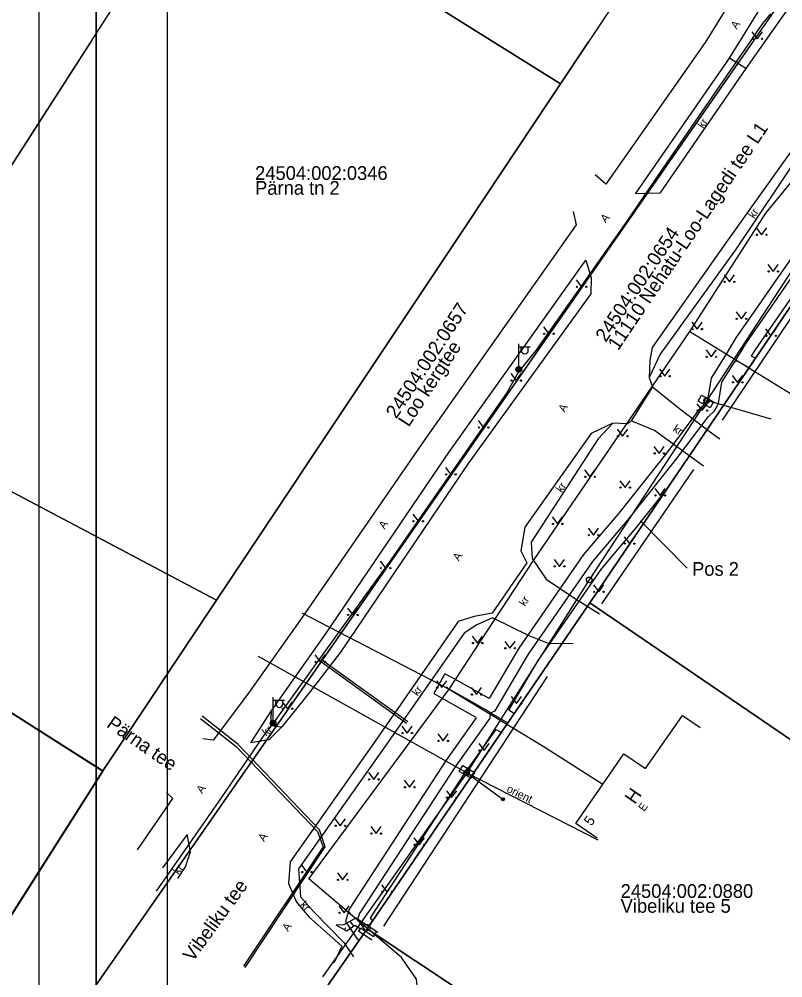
# Model space of a CAD drawing. Extents: x 553261 to 553443, y 6588794 to 6589074.
# Drawn here: x 553336.5 to 553403.3, y 6588946 to 6589029.9 of the extents above; entities that cross this region are included whole.
import ezdxf

# ---------------------------------------------------------------- set-up
doc = ezdxf.new("R2010")
doc.units = 0
for name, color, linetype in [('ELRAJATISMP', 7, 'Continuous'), ('HALJASTUS', 7, 'Continuous'), ('HOONE', 7, 'Continuous'), ('KASUTUSALA', 7, 'Continuous'), ('KPKAABEL', 7, 'Continuous'), ('MPKAABEL', 7, 'Continuous'), ('MPOHULIIN', 7, 'Continuous'), ('PIIR', 7, 'Continuous'), ('PIIRIMLEITUD', 7, 'Continuous'), ('POST', 7, 'Continuous'), ('PR_SIDE', 7, 'Continuous'), ('RAJATIS', 7, 'Continuous'), ('RELJEEF', 7, 'Continuous'), ('SITRASS', 7, 'Continuous'), ('TEE', 7, 'Continuous'), ('VORMISTUS_1', 7, 'Continuous')]:
    doc.layers.add(name, color=color, linetype=linetype)

msp = doc.modelspace()

# ---------------------------------------------------------------- linework, layer by layer
at = {"layer": 'ELRAJATISMP'}
for p, q in [((553396.633, 6588996.743), (553396.34, 6588996.222)), ((553396.869, 6588996.61), (553396.577, 6588996.089)), ((553375.732, 6588964.342), (553375.427, 6588963.83)), ((553375.966, 6588964.203), (553375.66, 6588963.691))]:
    msp.add_line(p, q, dxfattribs=at)
for points in [[(553396.23, 6588996.969), (553397.272, 6588996.384), (553396.979, 6588995.863), (553395.938, 6588996.448)], [(553375.336, 6588964.579), (553376.362, 6588963.967), (553376.056, 6588963.454), (553375.03, 6588964.066)]]:
    msp.add_lwpolyline(points, close=True, dxfattribs=at)
at = {"layer": 'HALJASTUS'}
for p, q in [((553400.647, 6589028.768), (553401.11, 6589028.161)), ((553401.11, 6589028.161), (553401.556, 6589028.768)), ((553401.025, 6589011.625), (553401.488, 6589011.018)), ((553401.488, 6589011.018), (553401.934, 6589011.625)), ((553402.039, 6589008.412), (553402.502, 6589007.806)), ((553402.502, 6589007.806), (553402.948, 6589008.412)), ((553398.203, 6589007.497), (553398.666, 6589006.891)), ((553398.666, 6589006.891), (553399.112, 6589007.497)), ((553385.257, 6589007.065), (553385.721, 6589006.458)), ((553385.721, 6589006.458), (553386.166, 6589007.065)), ((553405.456, 6589005.84), (553398.044, 6588994.79)), ((553399.253, 6589004.26), (553399.716, 6589003.654)), ((553399.716, 6589003.654), (553400.162, 6589004.26)), ((553382.398, 6589002.963), (553382.861, 6589002.356)), ((553382.861, 6589002.356), (553383.307, 6589002.963)), ((553395.38, 6589003.37), (553395.844, 6589002.764)), ((553395.844, 6589002.764), (553396.289, 6589003.37)), ((553401.841, 6589002.77), (553402.304, 6589002.163)), ((553402.304, 6589002.163), (553402.75, 6589002.77)), ((553396.625, 6589000.943), (553397.088, 6589000.336)), ((553397.088, 6589000.336), (553397.534, 6589000.943)), ((553379.539, 6588998.861), (553380.002, 6588998.254)), ((553380.002, 6588998.254), (553380.448, 6588998.861)), ((553392.558, 6588999.243), (553393.021, 6588998.636)), ((553393.021, 6588998.636), (553393.467, 6588999.243)), ((553398.925, 6588998.708), (553399.389, 6588998.101)), ((553399.389, 6588998.101), (553399.834, 6588998.708)), ((553395.83, 6588996.233), (553396.294, 6588995.627)), ((553396.294, 6588995.627), (553396.739, 6588996.233)), ((553376.68, 6588994.759), (553377.143, 6588994.153)), ((553377.143, 6588994.153), (553377.589, 6588994.759)), ((553388.86, 6588993.99), (553389.323, 6588993.383)), ((553389.323, 6588993.383), (553389.769, 6588993.99)), ((553392.065, 6588992.491), (553392.528, 6588991.885)), ((553392.528, 6588991.885), (553392.974, 6588992.491)), ((553373.82, 6588990.658), (553374.284, 6588990.051)), ((553374.284, 6588990.051), (553374.729, 6588990.658)), ((553386.003, 6588990.441), (553386.467, 6588989.835)), ((553386.467, 6588989.835), (553386.912, 6588990.441)), ((553395.523, 6588990.474), (553387.478, 6588978.735)), ((553389.075, 6588989.498), (553389.538, 6588988.891)), ((553389.538, 6588988.891), (553389.984, 6588989.498)), ((553392.138, 6588988.816), (553392.601, 6588988.209)), ((553392.601, 6588988.209), (553393.047, 6588988.816)), ((553370.961, 6588986.556), (553371.424, 6588985.949)), ((553371.424, 6588985.949), (553371.87, 6588986.556)), ((553383.169, 6588986.322), (553383.632, 6588985.716)), ((553383.632, 6588985.716), (553384.078, 6588986.322)), ((553386.303, 6588985.337), (553386.766, 6588984.73)), ((553386.766, 6588984.73), (553387.212, 6588985.337)), ((553389.457, 6588984.595), (553389.92, 6588983.988)), ((553389.92, 6588983.988), (553390.366, 6588984.595)), ((553368.102, 6588982.454), (553368.565, 6588981.847)), ((553368.565, 6588981.847), (553369.011, 6588982.454)), ((553383.326, 6588982.607), (553383.79, 6588982)), ((553383.79, 6588982), (553384.235, 6588982.607)), ((553386.776, 6588980.375), (553387.239, 6588979.768)), ((553387.239, 6588979.768), (553387.685, 6588980.375)), ((553365.243, 6588978.352), (553365.706, 6588977.745)), ((553365.706, 6588977.745), (553366.152, 6588978.352)), ((553376.168, 6588975.898), (553376.631, 6588975.291)), ((553376.631, 6588975.291), (553377.077, 6588975.898)), ((553379.005, 6588975.44), (553379.468, 6588974.833)), ((553379.468, 6588974.833), (553379.914, 6588975.44)), ((553362.383, 6588974.25), (553362.847, 6588973.644)), ((553362.847, 6588973.644), (553363.292, 6588974.25)), ((553373.04, 6588971.997), (553373.503, 6588971.39)), ((553373.503, 6588971.39), (553373.949, 6588971.997)), ((553376.076, 6588971.387), (553376.54, 6588970.78)), ((553376.54, 6588970.78), (553376.985, 6588971.387)), ((553379.566, 6588970.613), (553380.029, 6588970.006)), ((553380.029, 6588970.006), (553380.475, 6588970.613)), ((553359.524, 6588970.149), (553359.988, 6588969.542)), ((553359.988, 6588969.542), (553360.433, 6588970.149)), ((553370.005, 6588968.025), (553370.468, 6588967.419)), ((553370.468, 6588967.419), (553370.914, 6588968.025)), ((553373.148, 6588967.334), (553373.612, 6588966.727)), ((553373.612, 6588966.727), (553374.057, 6588967.334)), ((553376.734, 6588966.492), (553377.197, 6588965.886)), ((553377.197, 6588965.886), (553377.643, 6588966.492)), ((553367.08, 6588963.97), (553367.544, 6588963.363)), ((553367.544, 6588963.363), (553367.989, 6588963.97)), ((553370.22, 6588963.281), (553370.684, 6588962.674)), ((553370.684, 6588962.674), (553371.129, 6588963.281)), ((553373.902, 6588962.372), (553374.365, 6588961.765)), ((553374.365, 6588961.765), (553374.811, 6588962.372)), ((553364.155, 6588959.915), (553364.619, 6588959.308)), ((553364.619, 6588959.308), (553365.064, 6588959.915)), ((553367.292, 6588959.228), (553367.755, 6588958.622)), ((553367.755, 6588958.622), (553368.201, 6588959.228)), ((553371.069, 6588958.251), (553371.533, 6588957.645)), ((553371.533, 6588957.645), (553371.978, 6588958.251)), ((553361.231, 6588955.859), (553361.694, 6588955.253)), ((553361.694, 6588955.253), (553362.14, 6588955.859)), ((553364.364, 6588955.175), (553364.827, 6588954.569)), ((553364.827, 6588954.569), (553365.273, 6588955.175)), ((553368.237, 6588954.131), (553368.701, 6588953.524)), ((553368.701, 6588953.524), (553369.146, 6588954.131)), ((553364.493, 6588952.299), (553364.956, 6588951.693)), ((553364.956, 6588951.693), (553365.402, 6588952.299))]:
    msp.add_line(p, q, dxfattribs=at)
msp.add_lwpolyline([(553382.726, 6588972.365), (553376.514, 6588962.896), (553368.408, 6588950.506)], dxfattribs=at)
for centre in [(553400.709, 6589028.161), (553401.538, 6589028.161), (553401.087, 6589011.018), (553401.916, 6589011.018), (553402.101, 6589007.806), (553402.93, 6589007.806), (553385.32, 6589006.458), (553386.148, 6589006.458), (553398.265, 6589006.891), (553399.094, 6589006.891), (553399.315, 6589003.654), (553400.144, 6589003.654), (553382.46, 6589002.356), (553383.289, 6589002.356), (553395.443, 6589002.764), (553396.271, 6589002.764), (553401.903, 6589002.163), (553402.732, 6589002.163), (553396.687, 6589000.336), (553397.516, 6589000.336), (553379.601, 6588998.254), (553380.43, 6588998.254), (553392.62, 6588998.636), (553393.449, 6588998.636), (553398.988, 6588998.101), (553399.816, 6588998.101), (553395.893, 6588995.627), (553396.722, 6588995.627), (553376.742, 6588994.153), (553377.571, 6588994.153), (553388.922, 6588993.383), (553389.751, 6588993.383), (553392.127, 6588991.885), (553392.956, 6588991.885), (553373.883, 6588990.051), (553374.711, 6588990.051), (553386.066, 6588989.835), (553386.894, 6588989.835), (553389.137, 6588988.891), (553389.966, 6588988.891), (553392.2, 6588988.209), (553393.029, 6588988.209), (553371.023, 6588985.949), (553371.852, 6588985.949), (553383.231, 6588985.716), (553384.06, 6588985.716), (553386.365, 6588984.73), (553387.194, 6588984.73), (553389.519, 6588983.988), (553390.348, 6588983.988), (553383.389, 6588982), (553384.217, 6588982), (553368.164, 6588981.847), (553368.993, 6588981.847), (553386.838, 6588979.768), (553387.667, 6588979.768), (553365.305, 6588977.745), (553366.134, 6588977.745), (553376.23, 6588975.291), (553377.059, 6588975.291), (553379.067, 6588974.833), (553379.896, 6588974.833), (553362.446, 6588973.644), (553363.275, 6588973.644), (553373.102, 6588971.39), (553373.931, 6588971.39), (553376.139, 6588970.78), (553376.968, 6588970.78), (553359.587, 6588969.542), (553360.415, 6588969.542), (553379.628, 6588970.006), (553380.457, 6588970.006), (553370.067, 6588967.419), (553370.896, 6588967.419), (553373.211, 6588966.727), (553374.039, 6588966.727), (553376.796, 6588965.886), (553377.625, 6588965.886), (553367.142, 6588963.363), (553367.971, 6588963.363), (553370.283, 6588962.674), (553371.111, 6588962.674), (553373.964, 6588961.765), (553374.793, 6588961.765), (553364.218, 6588959.308), (553365.047, 6588959.308), (553367.354, 6588958.622), (553368.183, 6588958.622), (553371.132, 6588957.645), (553371.961, 6588957.645), (553361.293, 6588955.253), (553362.122, 6588955.253), (553364.426, 6588954.569), (553365.255, 6588954.569), (553368.3, 6588953.524), (553369.128, 6588953.524), (553364.555, 6588951.693), (553365.384, 6588951.693)]:
    msp.add_circle(centre, 0.055, dxfattribs=at)
at = {"layer": 'HOONE'}
msp.add_lwpolyline([(553387.1, 6588958.21), (553385.22, 6588959.51), (553389.44, 6588965.6), (553391.32, 6588964.3), (553394.57, 6588968.96), (553396.12, 6588967.9)], dxfattribs=at)
at = {"layer": 'KASUTUSALA'}
msp.add_lwpolyline([(553404.707, 6589009.859), (553399.243, 6589001.994), (553398.806, 6589001.279), (553398.467, 6589000.724), (553398.067, 6589000.069), (553397.062, 6588998.477), (553396.76, 6588996.579), (553396.566, 6588996.228), (553396.097, 6588995.804), (553393.172, 6588991.911), (553388.98, 6588986.655), (553385.917, 6588983.034), (553380.244, 6588974.844), (553377.649, 6588970.442), (553374.649, 6588972.122), (553373.776, 6588972.611), (553372.799, 6588970.866), (553373.671, 6588970.378), (553376.425, 6588968.835), (553376.522, 6588968.745), (553373.871, 6588965.038), (553365.384, 6588952.009), (553365.067, 6588950.917), (553366.023, 6588949.539), (553366.236, 6588949.233), (553366.97, 6588950.29), (553367.45, 6588950.992), (553367.274, 6588951.246), (553375.523, 6588963.91), (553378.26, 6588967.737), (553378.715, 6588967.474), (553379.847, 6588969.129), (553379.782, 6588969.167), (553379.362, 6588969.41), (553381.93, 6588973.766), (553387.507, 6588981.816), (553390.525, 6588985.385), (553393.109, 6588988.624), (553398.874, 6588997.139), (553399.821, 6588998.537), (553400.943, 6589000.194), (553400.921, 6589000.208), (553400.613, 6589000.401), (553400.919, 6589000.902), (553406.271, 6589008.606)], dxfattribs=at)
at = {"layer": 'KPKAABEL'}
for points in [[(553352.396, 6588968.693), (553355.51, 6588966.24), (553362.63, 6588958.79), (553363.12, 6588957.47), (553356.16, 6588947.024)], [(553356.304, 6588946.897), (553363.29, 6588957.47), (553362.79, 6588958.96), (553355.67, 6588966.41), (553352.533, 6588968.882)]]:
    msp.add_lwpolyline(points, dxfattribs=at)
at = {"layer": 'MPKAABEL'}
msp.add_line((553375.68, 6588963.935), (553387.15, 6588958.07), dxfattribs=at)
for points in [[(553402.257, 6589030.331), (553401.56, 6589029.493), (553392.545, 6589016.411), (553389.649, 6589012.117), (553381.74, 6589000.899), (553380.207, 6588999.016), (553379.219, 6588997.231), (553369.043, 6588982.568), (553359.555, 6588969.425), (553358.783, 6588968.309), (553357.879, 6588967.138), (553354.209, 6588961.743), (553348.518, 6588953.579)], [(553402.257, 6589030.331), (553401.56, 6589029.493), (553392.545, 6589016.411), (553389.649, 6589012.117), (553381.74, 6589000.899), (553380.207, 6588999.016), (553379.219, 6588997.231), (553369.043, 6588982.568), (553359.555, 6588969.425), (553358.783, 6588968.309), (553357.879, 6588967.138), (553354.209, 6588961.743), (553348.518, 6588953.579)], [(553362.874, 6588973.709), (553370.414, 6588968.272)], [(553362.978, 6588973.851), (553370.524, 6588968.422)]]:
    msp.add_lwpolyline(points, dxfattribs=at)
at = {"layer": 'MPOHULIIN'}
for points in [[(553407.936, 6589013.677), (553396.681, 6588996.514), (553396.681, 6588996.514), (553386.407, 6588980.817), (553375.68, 6588963.935), (553363.057, 6588946.078)], [(553402.318, 6588994.883), (553396.681, 6588996.514)], [(553375.68, 6588963.935), (553357.463, 6588974.128)]]:
    msp.add_lwpolyline(points, dxfattribs=at)
at = {"layer": 'PIIR'}
for points in [[(553398.49, 6589073.95), (553400.8, 6589049.61), (553383.89, 6589024.22), (553352.89, 6589043.6), (553339.8, 6589053.09), (553358.63, 6589067.61)], [(553352.89, 6589043.6), (553383.89, 6589024.22), (553353.8, 6588979.04), (553322.14, 6588995.79)], [(553343.85, 6588964.09), (553318.22, 6588923.75), (553292.18, 6588941.51), (553317.25, 6588980.99)], [(553366.97, 6588950.29), (553386.47, 6588978.82), (553419.97, 6588955.97), (553401.3, 6588927.47)], [(553401.3, 6588927.47), (553381.71, 6588898.9), (553347.5, 6588922.26), (553366.97, 6588950.29)]]:
    msp.add_lwpolyline(points, close=True, dxfattribs=at)
for points in [[(553269.61, 6588823.387), (553275.1, 6588838.43), (553306.34, 6588891.77), (553312.93, 6588901.87), (553404.2, 6589032.89), (553408.34, 6589040.49)], [(553431.953, 6589028.538), (553426.41, 6589023.65), (553416.94, 6589023.42), (553405.24, 6589006.54), (553386.47, 6588978.82), (553366.97, 6588950.29), (553347.5, 6588922.26), (553328.32, 6588893.48), (553310.97, 6588866.48), (553295.9, 6588840.93), (553293.3, 6588836.47), (553287.77, 6588819.195)], [(553400.72, 6589027.895), (553312.93, 6588901.87), (553306.34, 6588891.77), (553275.1, 6588838.43), (553278.46, 6588847.64), (553296.63, 6588881.81), (553313.47, 6588914.66), (553318.15, 6588923.71), (553343.84, 6588964.11), (553353.8, 6588979.04), (553383.89, 6589024.22), (553386.338, 6589027.895)], [(553292.469, 6589027.895), (553298.08, 6589020.22), (553322.14, 6588995.79), (553353.8, 6588979.04), (553343.84, 6588964.11), (553317.25, 6588980.99), (553291.21, 6588997.51), (553290.08, 6589002.89), (553293.13, 6589008.65), (553286.68, 6589017.98), (553280.69, 6589021.2), (553275.792, 6589027.895)], [(553342.789, 6589027.895), (553322.14, 6588995.79), (553298.08, 6589020.22), (553292.469, 6589027.895)], [(553434.11, 6588976.398), (553419.97, 6588955.97), (553386.47, 6588978.82), (553405.24, 6589006.54), (553434.11, 6588987.72)]]:
    msp.add_lwpolyline(points, dxfattribs=at)
at = {"layer": 'PIIRIMLEITUD'}
msp.add_circle((553366.946, 6588950.407), 0.285, dxfattribs=at)
at = {"layer": 'POST'}
for p, q in [((553380.235, 6588999.468), (553380.235, 6589001.468)), ((553380.235, 6589001.218), (553381.235, 6589001.218)), ((553380.462, 6589000.897), (553380.462, 6589001.218)), ((553381.075, 6589000.897), (553381.075, 6589001.218)), ((553380.235, 6588999.218), (553380.235, 6588999.218)), ((553358.743, 6588968.542), (553358.743, 6588970.542)), ((553358.743, 6588970.292), (553359.743, 6588970.292)), ((553358.97, 6588969.971), (553358.97, 6588970.292)), ((553359.582, 6588969.971), (553359.582, 6588970.292)), ((553358.743, 6588968.292), (553358.743, 6588968.292))]:
    msp.add_line(p, q, dxfattribs=at)
msp.add_lwpolyline([(553375.68, 6588963.935), (553378.85, 6588961.62)], dxfattribs=at)
for centre, radius in [((553380.235, 6588999.218), 0.25), ((553380.235, 6588999.218), 0.225), ((553380.235, 6588999.218), 0.2), ((553380.235, 6588999.218), 0.175), ((553380.235, 6588999.218), 0.15), ((553380.235, 6588999.218), 0.125), ((553380.235, 6588999.218), 0.1), ((553380.235, 6588999.218), 0.075), ((553380.235, 6588999.218), 0.05), ((553380.235, 6588999.218), 0.025), ((553396.681, 6588996.514), 0.25), ((553386.407, 6588980.817), 0.25), ((553358.743, 6588968.292), 0.25), ((553358.743, 6588968.292), 0.225), ((553358.743, 6588968.292), 0.2), ((553358.743, 6588968.292), 0.175), ((553358.743, 6588968.292), 0.15), ((553358.743, 6588968.292), 0.125), ((553358.743, 6588968.292), 0.1), ((553358.743, 6588968.292), 0.075), ((553358.743, 6588968.292), 0.05), ((553358.743, 6588968.292), 0.025), ((553375.68, 6588963.935), 0.25), ((553378.85, 6588961.62), 0.125), ((553378.85, 6588961.62), 0.105), ((553378.85, 6588961.62), 0.0851), ((553378.85, 6588961.62), 0.0651), ((553378.85, 6588961.62), 0.0451), ((553378.85, 6588961.62), 0.0251), ((553378.85, 6588961.62), 0.00511)]:
    msp.add_circle(centre, radius, dxfattribs=at)
for centre in [(553380.768, 6589000.897), (553359.276, 6588969.971)]:
    msp.add_arc(centre, 0.306, 180, 0, dxfattribs=at)
at = {"layer": 'PR_SIDE'}
for points in [[(553399.139, 6588999.905), (553400.081, 6589001.448), (553405.489, 6589009.233), (553408.532, 6589012.542), (553409.554, 6589014.823), (553413.47, 6589020.515), (553414.867, 6589022.525), (553415.143, 6589022.641), (553415.48, 6589022.56), (553416.124, 6589022.242)], [(553377.777, 6588969.173), (553378.164, 6588969.346), (553381.087, 6588974.305), (553386.712, 6588982.425), (553389.753, 6588986.02), (553393.963, 6588991.298), (553396.839, 6588995.127), (553397.36, 6588995.599), (553397.72, 6588996.248), (553398.017, 6588998.116), (553398.919, 6588999.544), (553399.139, 6588999.905)], [(553399.139, 6588999.905), (553399.361, 6588999.986), (553399.805, 6588999.727), (553400.389, 6588999.361)], [(553377.777, 6588969.173), (553377.364, 6588969.456), (553374.16, 6588971.25)], [(553366.845, 6588950.11), (553366.16, 6588951.096), (553366.303, 6588951.587), (553374.697, 6588964.474), (553377.731, 6588968.716), (553377.777, 6588969.173)], [(553377.777, 6588969.173), (553379.281, 6588968.302)]]:
    msp.add_lwpolyline(points, dxfattribs=at)
at = {"layer": 'RAJATIS'}
msp.add_lwpolyline([(553367.515, 6588949.587), (553366.408, 6588950.341), (553366.224, 6588950.119), (553367.381, 6588949.337)], dxfattribs=at)
at = {"layer": 'RELJEEF'}
for p, q in [((553365.809, 6588950.512), (553365.487, 6588950.96)), ((553364.981, 6588950.193), (553365.097, 6588950.403)), ((553366.687, 6588950.151), (553366.748, 6588950.25)), ((553367.515, 6588949.587), (553367.789, 6588950.04))]:
    msp.add_line(p, q, dxfattribs=at)
for points in [[(553367.903, 6588949.966), (553365.97, 6588951.233), (553364.905, 6588950.631), (553364.255, 6588950.595)], [(553366.362, 6588950.285), (553365.891, 6588950.571), (553365.198, 6588950.073), (553364.255, 6588950.595)]]:
    msp.add_lwpolyline(points, dxfattribs=at)
at = {"layer": 'SITRASS'}
for points in [[(553371.515, 6588943.799), (553371.28, 6588945.87), (553369.98, 6588947.79), (553361.86, 6588954.66), (553374.16, 6588971.25), (553381.59, 6588982.6), (553395.2, 6589002.56), (553401.87, 6589012.9), (553411.9, 6589025.12), (553419.37, 6589020.03), (553424.388, 6589016.672)], [(553395.2, 6589002.56), (553403.55, 6588997.42), (553409.017, 6588994.134)], [(553361.245, 6588977.942), (553374.16, 6588971.25)], [(553374.16, 6588971.25), (553382.37, 6588966.28), (553387.607, 6588962.955)]]:
    msp.add_lwpolyline(points, dxfattribs=at)
at = {"layer": 'TEE'}
msp.add_line((553400.105, 6589025.557), (553398.689, 6589026.473), dxfattribs=at)
for points in [[(553402.191, 6589038.206), (553399.566, 6589032.707), (553396.547, 6589027.841), (553387.864, 6589015.454), (553386.933, 6589016.246)], [(553407.629, 6589036.196), (553403.138, 6589029.864), (553400.105, 6589025.557), (553392.597, 6589014.643), (553390.443, 6589014.592), (553398.689, 6589026.473), (553401.561, 6589031.119), (553404.616, 6589037.375)], [(553404.003, 6589018.245), (553398.361, 6589010.315), (553391.908, 6589001.161), (553391.7, 6589000), (553391.649, 6588998.522), (553391.943, 6588997.694), (553390.065, 6588994.733), (553389.77, 6588994.47), (553388.465, 6588994.527), (553386.58, 6588993.615), (553380.779, 6588985.433), (553380.409, 6588983.357), (553380.953, 6588982.306), (553377.917, 6588977.901), (553376.347, 6588977.601), (553374.927, 6588977.176), (553367.932, 6588967.072), (553360.219, 6588956.151), (553360.094, 6588954.264), (553360.792, 6588952.606), (553361.86, 6588951.349), (553364.755, 6588948.771), (553364.058, 6588947.276)], [(553405.552, 6589018.694), (553404.957, 6589018.27), (553399.27, 6589009.775), (553392.603, 6589000.577), (553391.649, 6588998.522)], [(553384.999, 6589013.041), (553385.27, 6589011.887), (553372.005, 6588993.105), (553361.24, 6588977.509), (553356.493, 6588970.798), (553353.497, 6588966.803), (553352.596, 6588966.904)], [(553356.791, 6588966.553), (553358.58, 6588969.335), (553363.328, 6588976.079), (553374.183, 6588992.053), (553386.117, 6589008.789), (553386.573, 6589007.238), (553386.533, 6589005.842), (553375.804, 6588990.988), (553364.649, 6588974.479), (553361.905, 6588970.943), (553359.496, 6588967.969), (553358.373, 6588966.828), (553356.791, 6588966.553)], [(553391.943, 6588997.694), (553394.325, 6588995.774), (553396.897, 6588993.829), (553397.834, 6588993.162)], [(553388.465, 6588994.527), (553387.194, 6588993.145), (553381.324, 6588984.115), (553381.396, 6588982.694), (553382.626, 6588980.866), (553385.197, 6588979.163), (553387.298, 6588977.857)], [(553396.391, 6588990.755), (553392.13, 6588993.886), (553390.065, 6588994.733)], [(553385.006, 6588975.238), (553382.907, 6588975.212), (553381.135, 6588975.914), (553377.931, 6588977.503), (553376.554, 6588976.877), (553375.447, 6588976.158), (553368.852, 6588966.683), (553360.976, 6588955.531), (553361.138, 6588953.099), (553362.277, 6588951.811), (553364.93, 6588949.104), (553365.77, 6588947.839)], [(553358.58, 6588969.335), (553358.507, 6588968.074), (553359.496, 6588967.969)], [(553346.873, 6588957.197), (553349.953, 6588961.703), (553349.424, 6588962.204)], [(553350.411, 6588954.688), (553351.082, 6588955.72), (553351.518, 6588957.009), (553351.228, 6588958.542), (553349.059, 6588955.637)]]:
    msp.add_lwpolyline(points, dxfattribs=at)
at = {"layer": 'VORMISTUS_1'}
msp.add_line((553390.904, 6588985.993), (553394.98, 6588981.844), dxfattribs=at)
for points in [[(553338.255, 6589062.04), (553443.255, 6589062.04), (553443.255, 6588913.54), (553338.255, 6588913.54)], [(553343.255, 6588919.04), (553438.255, 6588919.04), (553438.255, 6589056.54), (553343.255, 6589056.54)], [(553343.255, 6589056.54), (553438.255, 6589056.54), (553438.255, 6588919.04), (553343.255, 6588919.04)], [(553432.005, 6588932.04), (553349.505, 6588932.04), (553349.505, 6589037.04), (553432.005, 6589037.04)]]:
    msp.add_lwpolyline(points, close=True, dxfattribs=at)

# ---------------------------------------------------------------- texts
at = {"layer": 'HOONE'}
for s, height, rotation, p in [('H', 1.2, 55.41411, (553390.402, 6588961.108)), ('E', 0.7, 55.41411, (553391.221, 6588960.499)), ('5', 0.9, 55.23477, (553386.597, 6588959.226))]:
    msp.add_text(s, height=height, rotation=rotation, dxfattribs=at).set_placement(p)
at = {"layer": 'MPKAABEL'}
msp.add_text('orient', height=0.7, rotation=333.19754, dxfattribs=at).set_placement((553379.115, 6588962.311))
at = {"layer": 'PIIR'}
for s, rotation, p in [('11110 Nehatu-Loo-Lagedi tee L1', 55.98329, (553388.93, 6589000.819)), ('24504:002:0654', 55.98329, (553387.853, 6589001.546)), ('24504:002:0657', 56.69618, (553369.517, 6588994.847)), ('Loo kergtee', 56.69618, (553370.604, 6588994.133))]:
    msp.add_text(s, height=1.2, rotation=rotation, dxfattribs=at).set_placement(p)
for s, p in [('24504:002:0346', (553357.163, 6589015.815)), ('Pärna tn 2', (553357.163, 6589014.515)), ('24504:002:0880', (553389.153, 6588952.992)), ('Vibeliku tee 5', (553389.153, 6588951.692))]:
    msp.add_text(s, height=1.2, dxfattribs=at).set_placement(p)
at = {"layer": 'TEE'}
for s, height, rotation, p in [('A', 0.7, 55.40858, (553399.302, 6589028.949)), ('kr', 0.7, 56.5358, (553396.395, 6589020.255)), ('kr', 0.7, 56.80313, (553400.841, 6589012.377)), ('A', 0.7, 47.21797, (553387.83, 6589012.017)), ('A', 0.7, 60.13872, (553384.25, 6588995.433)), ('kr', 0.7, 327.09867, (553393.66, 6588993.871)), ('kr', 0.7, 56.02738, (553384.003, 6588988.406)), ('A', 0.7, 56.05353, (553368.483, 6588985.215)), ('A', 0.7, 58.14297, (553374.992, 6588982.421)), ('kr', 0.7, 57.14215, (553380.783, 6588978.447)), ('kr', 0.7, 53.76199, (553371.392, 6588970.591)), ('Pärna tee', 1.2, 325.219, (553344.091, 6588968.01)), ('kr', 0.7, 38.35835, (553358.118, 6588967.108)), ('A', 0.7, 54.02928, (553352.525, 6588962.073)), ('A', 0.7, 56.51754, (553357.953, 6588957.868)), ('kr', 0.7, 54.33588, (553350.467, 6588954.982)), ('Vibeliku tee', 1.2, 54.0379, (553351.716, 6588947.34)), ('kr', 0.7, 311.60209, (553361.05, 6588952.344)), ('A', 0.7, 56.51754, (553360.053, 6588950.003))]:
    msp.add_text(s, height=height, rotation=rotation, dxfattribs=at).set_placement(p)
at = {"layer": 'VORMISTUS_1'}
msp.add_text('Pos 2', height=1.2, dxfattribs=at).set_placement((553395.403, 6588981.178))

doc.saveas('drawing.dxf')
